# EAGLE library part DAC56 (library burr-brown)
16-Bit Resolution DAC
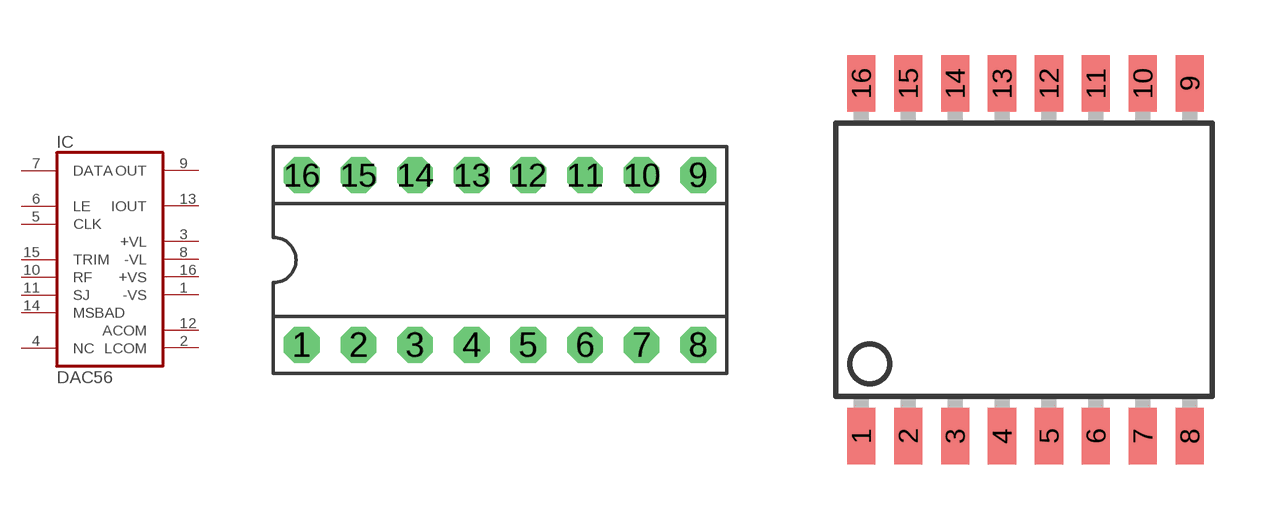
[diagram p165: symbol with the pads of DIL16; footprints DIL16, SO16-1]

Designator prefix IC

## DAC56P (OC_FARNELL: unknown; OC_NEWARK: unknown)  [DIL16]
1  -VS  pwr
2  LCOM  pwr
3  +VL  pwr
4  NC  nc
5  CLK  in
6  LE  in
7  DATA  in
8  -VL  pwr
9  OUT  out
10  RF  pas
11  SJ  pas
12  ACOM  pwr
13  IOUT  out
14  MSBAD  pas
15  TRIM  pas
16  +VS  pwr

## DAC56U (OC_FARNELL: unknown; OC_NEWARK: unknown)  [SO16-1]
Pads as for DIL16

## Footprint DIL16 (pad centres in mm)
Dual In Line
drill 0.813 pad 1.6 octagon: 1 -8.89,-3.81; 2 -6.35,-3.81; 3 -3.81,-3.81; 4 -1.27,-3.81; 5 1.27,-3.81; 6 3.81,-3.81; 7 6.35,-3.81; 8 8.89,-3.81; 9 8.89,3.81; 10 6.35,3.81; 11 3.81,3.81; 12 1.27,3.81; 13 -1.27,3.81; 14 -3.81,3.81; 15 -6.35,3.81; 16 -8.89,3.81

## Footprint SO16-1 (pad centres in mm)
Small Outline Package
smd 0.762 x 1.524: 1 -4.445,-4.775; 2 -3.175,-4.775; 3 -1.905,-4.775; 4 -0.635,-4.775; 5 0.635,-4.775; 6 1.905,-4.775; 7 3.175,-4.775; 8 4.445,-4.775; 9 4.445,4.775; 10 3.175,4.775; 11 1.905,4.775; 12 0.635,4.775; 13 -0.635,4.775; 14 -1.905,4.775; 15 -3.175,4.775; 16 -4.445,4.775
